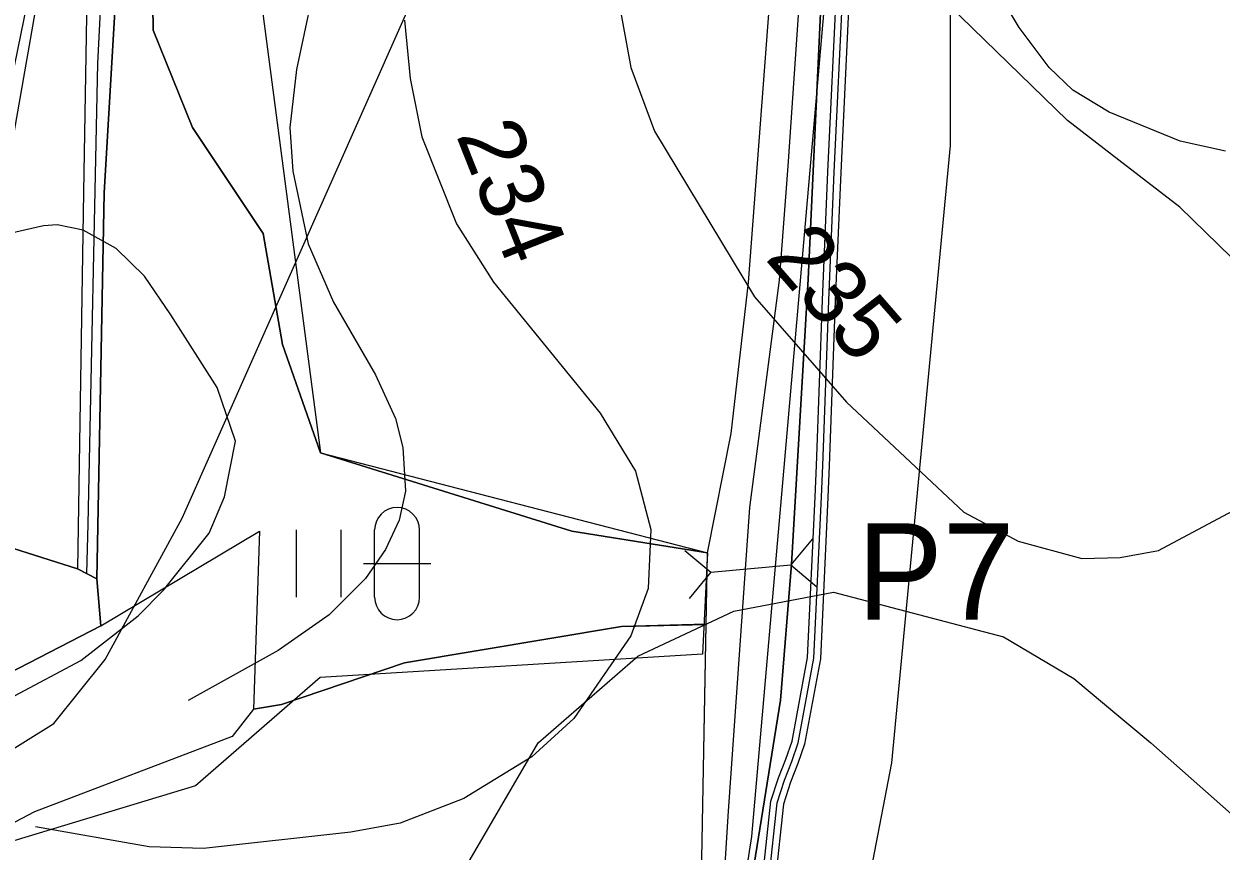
# Model space of a CAD drawing. Extents: x -662500 to -653478, y -1056827 to -1049993.
# Drawn here: x -660170.7 to -659984.1, y -1053168.4 to -1053039.4 of the extents above; entities that cross this region are included whole.
import ezdxf

# ---------------------------------------------------------------- set-up
doc = ezdxf.new("R2010")
doc.units = 0
for name, color, linetype in [('Vrstva 11', 7, 'Continuous'), ('Vrstva 17', 7, 'Continuous'), ('Vrstva 24', 7, 'Continuous'), ('Vrstva 30', 7, 'Continuous'), ('Vrstva 32', 7, 'Continuous'), ('Vrstva 37', 7, 'Continuous'), ('Vrstva 42', 7, 'Continuous'), ('Vrstva 47', 7, 'Continuous'), ('Vrstva 5', 7, 'Continuous'), ('Vrstva 50', 7, 'Continuous'), ('Vrstva 61', 7, 'Continuous'), ('Vrstva 7', 7, 'Continuous')]:
    doc.layers.add(name, color=color, linetype=linetype)

# ---------------------------------------------------------------- blocks, each defined once
blk = doc.blocks.new('PSZ017')
at = {"layer": 'Vrstva 17'}
for points in [[(-10, 3.75), (-6.25, 0), (-10, -3.75)], [(10, 3.75), (6.25, 0), (10, -3.75)], [(-6.25, 0), (6.25, 0)]]:
    blk.add_lwpolyline(points, dxfattribs=at)

msp = doc.modelspace()

# ---------------------------------------------------------------- linework, layer by layer
at = {"layer": 'Vrstva 11'}
msp.add_lwpolyline([(-660043.77, -1052964.52), (-660047.11, -1052995.9), (-660048.8, -1053020.58), (-660051.61, -1053061.61), (-660052.93, -1053079.39), (-660057.59, -1053114.8), (-660060.88, -1053162.14), (-660061.5, -1053172.08), (-660065.23, -1053196.24), (-660068.52, -1053209.73), (-660080.33, -1053244.37), (-660088.5, -1053263.64), (-660096.4, -1053281.22), (-660102.08, -1053296.45), (-660104.3, -1053303.24), (-660111.19, -1053332.15), (-660115.89, -1053363.94), (-660119.67, -1053410.57), (-660121.55, -1053443.11), (-660128.59, -1053535.41), (-660141.02, -1053666.13)], dxfattribs=at)
at = {"layer": 'Vrstva 24'}
for points in [[(-660331, -1053241.5), (-660301, -1053212), (-660278, -1053198), (-660227.5, -1053179), (-660190.5, -1053163), (-660174, -1053153.5), (-660166, -1053148.5), (-660158, -1053138.5), (-660146, -1053116.5), (-660094.29, -1053000), (-660092.5, -1052996), (-660076, -1052973.5), (-660055.5, -1052958.5), (-660034, -1052954)], [(-659728.49, -1053235.51), (-659755.5, -1053223.5), (-659901.5, -1053140), (-659970.5, -1053087.5), (-659990.5, -1053068), (-660000, -1053060.67), (-660008, -1053054.5), (-660026.5, -1053036.5), (-660039.5, -1053009.5), (-660040.38, -1053000), (-660042, -1052982.5), (-660034, -1052954)], [(-660163, -1053003.5), (-660174, -1053066.5), (-660178.5, -1053074), (-660183, -1053084.5), (-660192.5, -1053091.5), (-660213.5, -1053095), (-660260.5, -1053096.5), (-660299, -1053106), (-660322, -1053122.5), (-660356.5, -1053167.5), (-660401, -1053208), (-660418.5, -1053226), (-660434.5, -1053237.5)], [(-660081, -1053315.5), (-660096, -1053300), (-660112, -1053273), (-660119.5, -1053246), (-660118.5, -1053214.5), (-660111.5, -1053187.5), (-660090.5, -1053151.5), (-660075, -1053138), (-660060, -1053131), (-660044.5, -1053128), (-660018, -1053135), (-660007, -1053141.5), (-660000, -1053147.33), (-659995, -1053151.5), (-659934, -1053205.5), (-659879, -1053241.5), (-659798.5, -1053281), (-659752.13, -1053295.23)]]:
    msp.add_lwpolyline(points, dxfattribs=at)
msp.add_lwpolyline([(-660159.28, -1053125.93), (-660162.29, -1053124.36), (-660173.45, -1053120.87), (-660195.12, -1053121.66), (-660216.31, -1053120.87), (-660245.66, -1053113.43), (-660281.35, -1053120.12), (-660302.14, -1053126.44), (-660312.07, -1053128.99), (-660317.72, -1053134.2), (-660322.02, -1053144.73), (-660320.88, -1053178.8), (-660319.15, -1053180.6), (-660304.97, -1053184.86), (-660291.54, -1053190.52), (-660282.09, -1053190.79), (-660279.01, -1053183.69), (-660268.02, -1053173.58), (-660247.63, -1053156.17), (-660244.16, -1053154.52), (-660239.78, -1053153.33), (-660215.8, -1053151.27), (-660186.01, -1053147.33), (-660158.67, -1053133.25)], close=True, dxfattribs=at)
at = {"layer": 'Vrstva 30'}
msp.add_lwpolyline([(-660322.02, -1053144.73), (-660317.71, -1053134.2), (-660312.07, -1053128.99), (-660302.14, -1053126.44), (-660281.35, -1053120.12), (-660245.66, -1053113.43), (-660216.31, -1053120.87), (-660195.12, -1053121.66), (-660173.45, -1053120.87), (-660162.29, -1053124.36), (-660159.28, -1053125.93), (-660158.67, -1053133.25), (-660186.01, -1053147.33), (-660215.8, -1053151.27), (-660239.78, -1053153.33), (-660244.16, -1053154.52), (-660247.64, -1053156.17), (-660268.02, -1053173.58), (-660279.01, -1053183.69), (-660289.71, -1053175.98), (-660296.94, -1053171.46), (-660303.07, -1053164.35)], close=True, dxfattribs=at)
at = {"layer": 'Vrstva 32'}
msp.add_lwpolyline([(-660160.88, -1053125.12), (-660160.66, -1053117.41), (-660159.16, -1053045.6), (-660157.94, -1053021.94), (-660156.76, -1053017.77), (-660153.81, -1053014.23), (-660118.13, -1052962.6), (-660106.54, -1052947.23), (-660093.09, -1052938.1), (-660082.98, -1052933), (-660074.25, -1052924.36), (-660055.79, -1052908.21), (-660043.52, -1052897.56), (-659991.83, -1052849.55), (-659971.21, -1052829.43), (-659940.88, -1052799.92), (-659928.36, -1052782.89), (-659895.08, -1052736.55)], dxfattribs=at)
at = {"layer": 'Vrstva 37'}
msp.add_lwpolyline([(-660026.32, -1052991.73), (-660026.32, -1053058.37), (-660035.43, -1053154.64), (-660050.23, -1053231.54), (-659773.69, -1053361.27), (-659704.27, -1053171.81), (-659884.58, -1053081.65)], close=True, dxfattribs=at)
at = {"layer": 'Vrstva 42'}
msp.add_lwpolyline([(-660088.15, -1053276.4), (-660075.09, -1053253.54), (-660063.07, -1053219.83), (-660055.85, -1053184.99), (-660053.25, -1053160.83), (-660052.11, -1053157.3), (-660050.97, -1053154.4), (-660049.97, -1053151.48), (-660047.52, -1053138.32), (-660046.36, -1053113.18), (-660046.14, -1053108.29), (-660045.22, -1053082.55), (-660044.35, -1053062.53), (-660041.58, -1053004.07), (-660041.53, -1052996.23), (-660041.37, -1052990.33), (-660039.93, -1052981.98)], dxfattribs=at)
at = {"layer": 'Vrstva 47'}
for points in [[(-660056.84, -1053184.84), (-660054.23, -1053160.62), (-660053.05, -1053156.96), (-660051.91, -1053154.06), (-660050.94, -1053151.23), (-660048.52, -1053138.2), (-660047.36, -1053113.14), (-660047.14, -1053108.25), (-660046.22, -1053082.51), (-660045.35, -1053062.49), (-660042.58, -1053004.04)], [(-660040.58, -1053004.1), (-660043.35, -1053062.58), (-660044.22, -1053082.59), (-660045.14, -1053108.33), (-660045.36, -1053113.23), (-660046.52, -1053138.43), (-660049, -1053151.73), (-660050.03, -1053154.75), (-660051.17, -1053157.64), (-660052.26, -1053161.04), (-660054.86, -1053185.15)]]:
    msp.add_lwpolyline(points, dxfattribs=at)
at = {"layer": 'Vrstva 5'}
for points in [[(-660065.03, -1053172.38), (-660064.33, -1053133.08), (-660064.14, -1053121.91), (-660060.42, -1053103.31), (-660057.71, -1053079.73), (-660053.97, -1053030.21), (-660051.01, -1052978.13), (-660053.61, -1052965.27), (-660075.23, -1052942.33), (-660081.53, -1052935.22), (-660084.53, -1052931.2), (-660114.36, -1052901.46), (-660145.01, -1052867.3), (-660170.48, -1052845.46), (-660192.36, -1052831.33), (-660221.62, -1052816.23), (-660262.56, -1052793.72), (-660278.43, -1052777.59), (-660290.42, -1052757.76)], [(-660060.79, -1052911.01), (-660076.02, -1052922.76), (-660084.53, -1052931.2), (-660094.75, -1052935.76), (-660109.05, -1052945.68), (-660148.01, -1053001.78), (-660158.78, -1053017), (-660160.63, -1053022.92), (-660161.37, -1053065.69), (-660162.29, -1053124.36), (-660159.28, -1053125.93), (-660158.13, -1053065.76), (-660155.45, -1053019.8), (-660144.4, -1053004.38), (-660112.49, -1052958.14), (-660104.22, -1052947.56), (-660092.12, -1052940.17), (-660081.53, -1052935.22), (-660071.92, -1052926.88), (-660059.01, -1052913.47), (-660047.02, -1052903.13)], [(-660126.59, -1053589.2), (-660118.91, -1053503.44), (-660111.89, -1053403.2), (-660108.8, -1053372.46), (-660103.38, -1053346.8), (-660096.52, -1053301.66), (-660093.7, -1053289.88), (-660091, -1053284.32), (-660083.08, -1053260.59), (-660074.85, -1053238.74), (-660066.72, -1053215.08), (-660061.35, -1053195.73), (-660057.3, -1053173.33), (-660052.73, -1053144.83), (-660051.02, -1053123.63), (-660048.41, -1053079.23), (-660046.22, -1053030.94), (-660043.45, -1052998.9), (-660040.02, -1052979.17), (-660007.4, -1053007.56), (-659984.03, -1053022.62), (-659883.53, -1053077.01), (-659802.22, -1053120.51), (-659716.54, -1053165.89)], [(-659716.54, -1053165.89), (-659802.22, -1053120.51), (-659883.53, -1053077.01), (-659984.03, -1053022.62), (-660007.4, -1053007.56), (-660040.02, -1052979.17), (-660043.45, -1052998.9), (-660046.22, -1053030.94), (-660048.41, -1053079.23), (-660051.02, -1053123.63), (-660052.73, -1053144.83), (-660057.3, -1053173.33), (-660061.35, -1053195.73), (-660066.72, -1053215.08), (-660074.85, -1053238.74), (-660083.08, -1053260.59), (-660091, -1053284.32), (-660093.7, -1053289.88), (-660096.52, -1053301.66), (-660103.38, -1053346.8), (-660108.8, -1053372.46), (-660111.89, -1053403.2), (-660118.91, -1053503.44), (-660126.59, -1053589.2)], [(-660128.25, -1053118.31), (-660128.25, -1053128.81)], [(-660121.25, -1053118.31), (-660121.25, -1053128.81)], [(-660116, -1053128.81), (-660116, -1053118.31)], [(-660109, -1053128.81), (-660109, -1053118.31)], [(-660117.75, -1053123.56), (-660107.25, -1053123.56)], [(-660065.03, -1053172.38), (-660064.33, -1053132.99), (-660077.5, -1053133.38), (-660111.34, -1053139.03), (-660130.49, -1053145.54), (-660134.88, -1053146.27), (-660138.22, -1053150.5), (-660169, -1053162.26), (-660188.45, -1053172.43)]]:
    msp.add_lwpolyline(points, dxfattribs=at)
for points in [[(-660081.53, -1052935.22), (-660092.12, -1052940.17), (-660104.22, -1052947.56), (-660112.49, -1052958.14), (-660144.4, -1053004.38), (-660150.73, -1053024.65), (-660150.51, -1053040.43), (-660144.36, -1053055.57), (-660133.37, -1053072.12), (-660130.34, -1053089.39), (-660124.45, -1053106.32), (-660085.27, -1053118.51), (-660064.14, -1053121.91), (-660060.42, -1053103.31), (-660057.71, -1053079.73), (-660053.97, -1053030.21), (-660051.01, -1052978.13), (-660053.61, -1052965.27), (-660075.23, -1052942.33)], [(-660144.4, -1053004.38), (-660155.45, -1053019.8), (-660158.13, -1053065.76), (-660159.28, -1053125.93), (-660158.67, -1053133.25), (-660133.92, -1053118.5), (-660134.88, -1053146.27), (-660130.49, -1053145.54), (-660111.34, -1053139.03), (-660077.5, -1053133.38), (-660064.33, -1053133.08), (-660064.14, -1053121.91), (-660085.27, -1053118.51), (-660124.45, -1053106.32), (-660130.34, -1053089.39), (-660133.37, -1053072.12), (-660144.36, -1053055.57), (-660150.51, -1053040.43), (-660150.73, -1053024.65)], [(-660158.78, -1053017), (-660160.63, -1053022.92), (-660161.37, -1053065.69), (-660162.29, -1053124.36), (-660173.45, -1053120.87), (-660175.03, -1053103.15), (-660176.15, -1053079.57), (-660175.58, -1053062.54), (-660169.18, -1053031.47)], [(-660320.88, -1053178.8), (-660322.02, -1053144.73), (-660317.71, -1053134.2), (-660312.07, -1053128.99), (-660302.14, -1053126.44), (-660281.35, -1053120.12), (-660245.66, -1053113.43), (-660216.31, -1053120.87), (-660195.12, -1053121.66), (-660173.45, -1053120.87), (-660162.29, -1053124.36), (-660159.28, -1053125.93), (-660158.67, -1053133.25), (-660186.01, -1053147.33), (-660215.8, -1053151.27), (-660239.78, -1053153.33), (-660244.16, -1053154.52), (-660247.68, -1053155.93), (-660268.02, -1053173.58), (-660279.01, -1053183.69), (-660282.09, -1053190.79), (-660291.54, -1053190.52), (-660304.97, -1053184.86), (-660319.15, -1053180.6)], [(-660261.56, -1053201.85), (-660298.9, -1053220.33), (-660277.59, -1053190.2), (-660279.01, -1053183.69), (-660268.02, -1053173.58), (-660247.68, -1053155.93), (-660244.16, -1053154.52), (-660239.78, -1053153.33), (-660215.8, -1053151.27), (-660186.01, -1053147.33), (-660158.67, -1053133.25), (-660133.92, -1053118.5), (-660134.88, -1053146.27), (-660138.22, -1053150.5), (-660169, -1053162.26), (-660188.45, -1053172.43), (-660205.94, -1053180.18), (-660252.52, -1053196.63)]]:
    msp.add_lwpolyline(points, close=True, dxfattribs=at)
for centre, start, end in [((-660112.5, -1053118.31), 0, 180), ((-660112.5, -1053128.81), 180, 0)]:
    msp.add_arc(centre, 3.5, start, end, dxfattribs=at)
at = {"layer": 'Vrstva 50'}
msp.add_lwpolyline([(-660435.07, -1052998.4), (-660338.47, -1052921.22), (-660327.47, -1053057.73), (-660321.24, -1053097.21), (-660175.03, -1053103.15), (-660174.83, -1053022.87), (-660135.14, -1053024.72), (-660124.45, -1053106.32), (-660064.14, -1053121.91), (-660064.92, -1053137.67), (-660124.48, -1053141.31), (-660143.9, -1053158.22), (-660224.98, -1053182.72), (-660282.65, -1053206.04), (-660302.63, -1053225.87), (-660408.17, -1053286.14), (-660457.22, -1053301.47), (-660422.63, -1053240.33), (-660404.5, -1053207.93), (-660439.36, -1053118.83)], close=True, dxfattribs=at)
at = {"layer": 'Vrstva 61'}
msp.add_lwpolyline([(-660040.21, -1052971.27), (-660052.48, -1053111.57), (-660057.25, -1053166.08), (-660064.24, -1053210.94), (-660077.54, -1053248.19), (-660090.91, -1053279.88), (-660093.08, -1053291.6)], dxfattribs=at)
at = {"layer": 'Vrstva 7'}
for p, q in [((-660124.8, -1053030.66), (-660128.2, -1053046.53)), ((-660015.53, -1053040.01), (-660020.78, -1053031.22)), ((-660077.89, -1053036.33), (-660076.05, -1053046.25)), ((-660111.33, -1053038.88), (-660110.48, -1053047.95)), ((-660010.86, -1053046.25), (-660015.53, -1053040.01)), ((-660128.2, -1053046.53), (-660129.19, -1053055.6)), ((-660076.05, -1053046.25), (-660072.36, -1053056.17)), ((-660007.17, -1053049.79), (-660010.86, -1053046.25)), ((-660110.48, -1053047.95), (-660108.64, -1053057.02)), ((-660001.5, -1053053.19), (-660007.17, -1053049.79)), ((-659990.45, -1053057.73), (-660001.5, -1053053.19)), ((-660129.19, -1053055.6), (-660128.76, -1053062.4)), ((-660072.36, -1053056.17), (-660056.77, -1053081.96)), ((-660108.64, -1053057.02), (-660103.26, -1053070.62)), ((-659983.36, -1053059.28), (-659990.45, -1053057.73)), ((-660128.76, -1053062.4), (-660126.35, -1053073.74)), ((-660167.59, -1053070.9), (-660172.38, -1053072.01)), ((-660165.47, -1053070.76), (-660167.59, -1053070.9)), ((-660161.41, -1053071.59), (-660165.47, -1053070.76)), ((-660103.26, -1053070.62), (-660097.45, -1053079.69)), ((-660156.26, -1053074.45), (-660161.41, -1053071.59)), ((-660151.86, -1053078.77), (-660156.26, -1053074.45)), ((-660126.35, -1053073.74), (-660122.39, -1053082.81)), ((-660147.75, -1053084.79), (-660151.86, -1053078.77)), ((-660097.45, -1053079.69), (-660080.86, -1053100.1)), ((-660056.77, -1053081.96), (-660042.46, -1053098.4)), ((-660122.39, -1053082.81), (-660115.87, -1053094.15)), ((-660140.53, -1053096.13), (-660147.75, -1053084.79)), ((-660115.87, -1053094.15), (-660112.75, -1053100.95)), ((-660137.69, -1053104.49), (-660140.53, -1053096.13)), ((-660042.46, -1053098.4), (-660024.18, -1053115.54)), ((-660112.75, -1053100.95), (-660111.62, -1053105.48)), ((-660080.86, -1053100.1), (-660075.34, -1053109.17)), ((-660139.39, -1053113.14), (-660137.69, -1053104.49)), ((-660111.62, -1053105.48), (-660111.19, -1053112.29)), ((-660075.34, -1053109.17), (-660072.93, -1053118.24)), ((-660111.19, -1053112.29), (-660112.18, -1053116.82)), ((-660141.8, -1053118.8), (-660139.39, -1053113.14)), ((-659993.85, -1053121.5), (-659978.97, -1053113.56)), ((-660024.18, -1053115.54), (-660015.68, -1053120.08)), ((-660112.18, -1053116.82), (-660114.31, -1053121.36)), ((-660148.89, -1053127.73), (-660141.8, -1053118.8)), ((-660072.93, -1053118.24), (-660073.35, -1053127.45)), ((-660114.31, -1053121.36), (-660117.43, -1053125.89)), ((-660015.68, -1053120.08), (-660005.76, -1053122.77)), ((-659999.8, -1053122.63), (-659993.85, -1053121.5)), ((-660005.76, -1053122.77), (-659999.8, -1053122.63)), ((-660117.43, -1053125.89), (-660123.1, -1053131.56)), ((-660152.86, -1053131.7), (-660148.89, -1053127.73)), ((-660073.35, -1053127.45), (-660076.05, -1053134.82)), ((-660161.78, -1053138.65), (-660152.86, -1053131.7)), ((-660123.1, -1053131.56), (-660131.03, -1053137.09)), ((-660076.05, -1053134.82), (-660084.97, -1053147.72)), ((-660131.03, -1053137.09), (-660145.06, -1053144.88)), ((-660172.13, -1053144.17), (-660161.78, -1053138.65)), ((-660084.97, -1053147.72), (-660091.49, -1053153.67)), ((-660091.49, -1053153.67), (-660102.12, -1053160.19)), ((-660102.12, -1053160.19), (-660112.04, -1053164.01)), ((-660112.04, -1053164.01), (-660119.7, -1053165.43)), ((-660151.16, -1053167.7), (-660168.83, -1053164.61)), ((-660119.7, -1053165.43), (-660142.65, -1053167.98)), ((-660142.65, -1053167.98), (-660151.16, -1053167.7))]:
    msp.add_line(p, q, dxfattribs=at)

# ---------------------------------------------------------------- block references
at = {"layer": 'Vrstva 17', "rotation": 5.27729085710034}
msp.add_blockref('PSZ017', (-660057.36, -1053124.35), dxfattribs=at)

# ---------------------------------------------------------------- texts
at = {"layer": 'Vrstva 17'}
msp.add_text('P7', height=15, rotation=360, dxfattribs=at).set_placement((-660040.81, -1053132.28))
at = {"layer": 'Vrstva 7'}
for s, rotation, p in [('234', 291.5942, (-660103.36, -1053056.77)), ('235', 311.0452, (-660055.29, -1053076.04))]:
    msp.add_text(s, height=10, rotation=rotation, dxfattribs=at).set_placement(p)

doc.saveas('drawing.dxf')
